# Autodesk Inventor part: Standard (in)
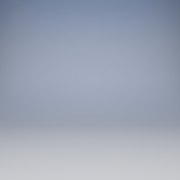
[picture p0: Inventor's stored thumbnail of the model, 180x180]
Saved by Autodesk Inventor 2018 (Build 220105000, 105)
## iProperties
Created: 2017-02
Part Number: Standard (in)
Material: Ogólny
Document SubType Name: Modeling
Density: 1 g/cm^3
Appearance: Domyślna
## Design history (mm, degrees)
